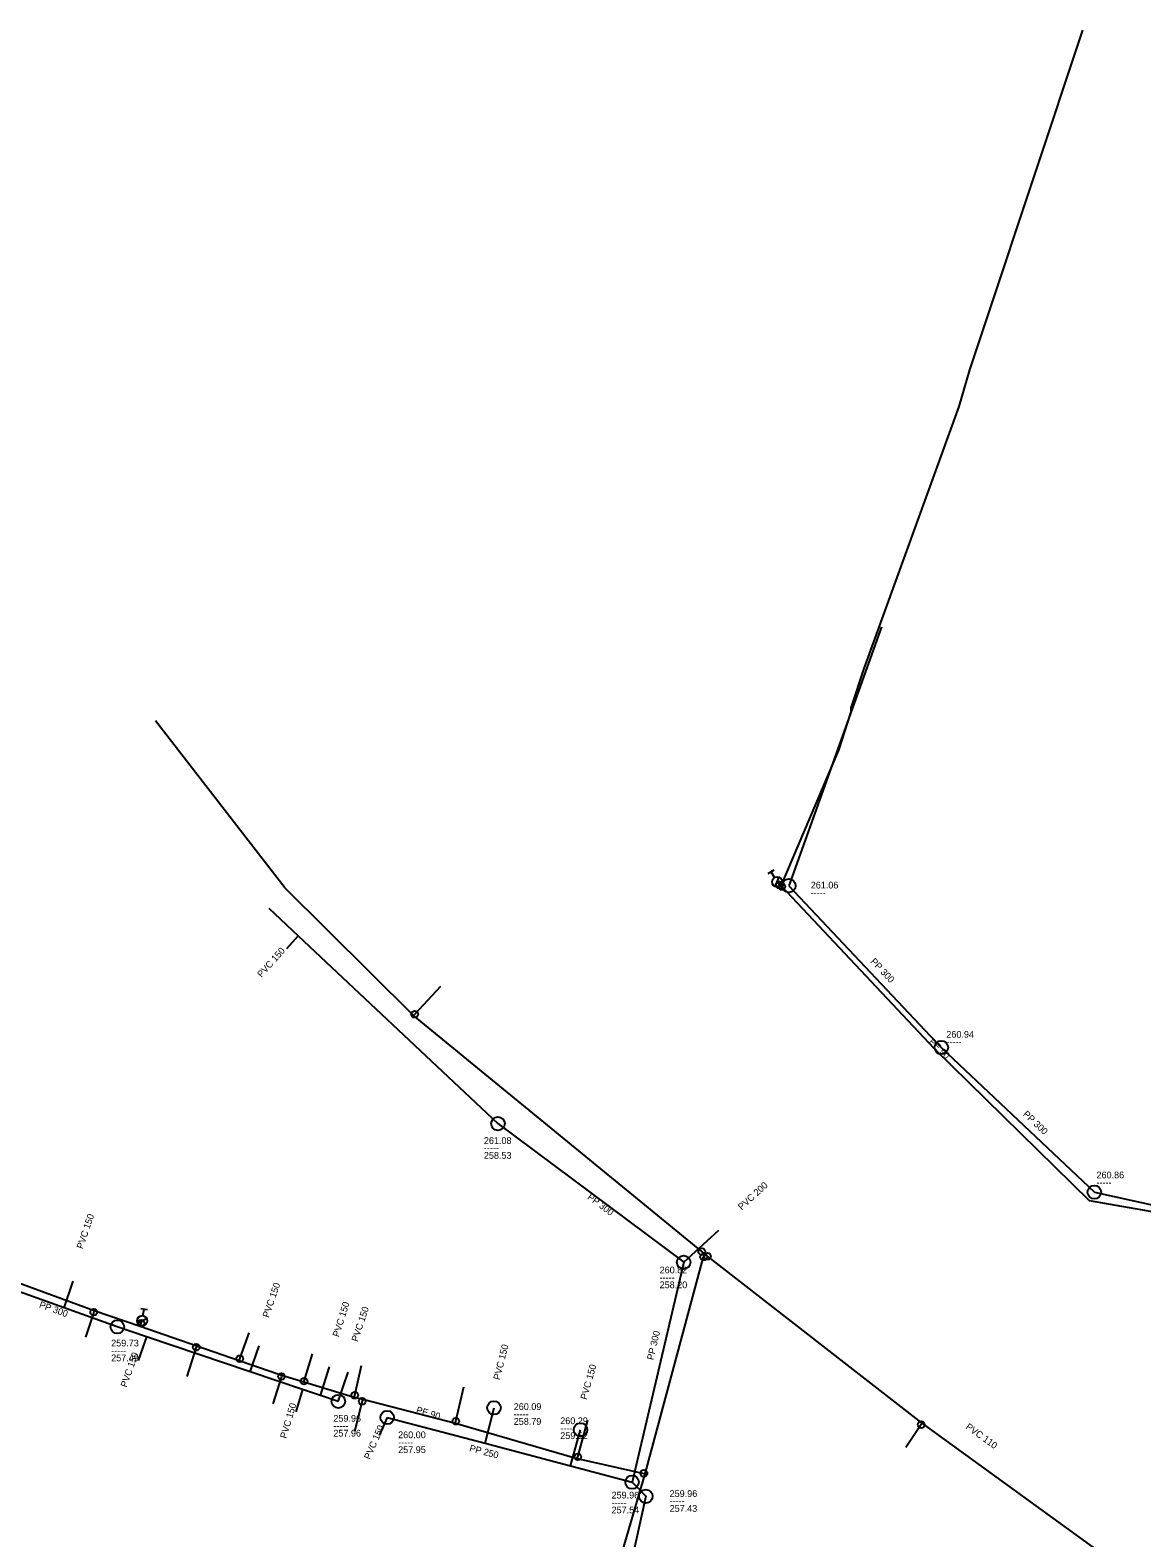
# Model space of a CAD drawing. Extents: x -771681 to -770485, y -1050143 to -1049574.
# Drawn here: x -771090.5 to -770925.9, y -1049898.6 to -1049675.1 of the extents above; entities that cross this region are included whole.
import ezdxf

# ---------------------------------------------------------------- set-up
doc = ezdxf.new("R2010")
doc.units = 0
doc.layers.add('Level 0', color=7, linetype='Continuous')

msp = doc.modelspace()

# ---------------------------------------------------------------- linework, layer by layer
at = {"layer": 'Level 0'}
for p, q in [((-770934.63, -1049675.12), (-770948.99, -1049718.19)), ((-770948.99, -1049718.19), (-770951.4, -1049725.46)), ((-770951.4, -1049725.46), (-770952.95, -1049730.91)), ((-770952.95, -1049730.91), (-770967.04, -1049769.75)), ((-770964.4, -1049763.54), (-770978.14, -1049801.92)), ((-770967.04, -1049769.75), (-770968.94, -1049775.57)), ((-770968.96, -1049776.14), (-770970.78, -1049781.83)), ((-770968.94, -1049775.57), (-770968.96, -1049776.14)), ((-771052.81, -1049802.25), (-771071.95, -1049777.49)), ((-770970.78, -1049781.83), (-770979.33, -1049801.95)), ((-770981.19, -1049800.09), (-770980.32, -1049799.59)), ((-770980.26, -1049800.71), (-770980.76, -1049799.84)), ((-770980.16, -1049802.05), (-770979.6, -1049800.66)), ((-770979.52, -1049801.81), (-770979.88, -1049801.36)), ((-771033.72, -1049821.15), (-771052.81, -1049802.25)), ((-770979.33, -1049801.95), (-770979.52, -1049801.81)), ((-770979.19, -1049802.05), (-770979.33, -1049801.95)), ((-770956.57, -1049826.09), (-770979.19, -1049802.05)), ((-770978.14, -1049801.92), (-770955.57, -1049825.89)), ((-771055.15, -1049805.27), (-771050.81, -1049809.36)), ((-771050.81, -1049809.36), (-771052.52, -1049811.28)), ((-771050.81, -1049809.36), (-771021.23, -1049837.18)), ((-771033.56, -1049820.97), (-771029.71, -1049816.81)), ((-771033.72, -1049821.15), (-771033.56, -1049820.97)), ((-770991.04, -1049856.14), (-771033.72, -1049821.15)), ((-770955.57, -1049825.89), (-770932.9, -1049847.34)), ((-770933.62, -1049848.6), (-770956.57, -1049826.09)), ((-771021.23, -1049837.18), (-770993.72, -1049857.73)), ((-770932.9, -1049847.34), (-770918.82, -1049850.46)), ((-770921.78, -1049850.71), (-770933.62, -1049848.6)), ((-770993.72, -1049857.73), (-770988.5, -1049852.98)), ((-771101.81, -1049857.24), (-771081.01, -1049864.88)), ((-770999.4, -1049889.07), (-770990.76, -1049856.93)), ((-770990.49, -1049856.6), (-770991.04, -1049856.14)), ((-770990.76, -1049856.93), (-770990.49, -1049856.6)), ((-770990.2, -1049856.84), (-770990.49, -1049856.6)), ((-770958.39, -1049881.57), (-770990.2, -1049856.84)), ((-770993.72, -1049857.73), (-771001.36, -1049890.32)), ((-771085.49, -1049864.48), (-771094.02, -1049861.43)), ((-771085.49, -1049864.48), (-771084.16, -1049860.54)), ((-771077.6, -1049867.3), (-771085.49, -1049864.48)), ((-771081.09, -1049865.13), (-771082.31, -1049868.84)), ((-771081.01, -1049864.88), (-771081.09, -1049865.13)), ((-771081.01, -1049864.88), (-771074.23, -1049867.21)), ((-771074.59, -1049866.74), (-771073.27, -1049866.04)), ((-771074.12, -1049864.58), (-771073.13, -1049864.75)), ((-771073.8, -1049865.65), (-771073.63, -1049864.67)), ((-771073.28, -1049868.76), (-771077.6, -1049867.3)), ((-771074.23, -1049867.21), (-771074.08, -1049866.75)), ((-771074.23, -1049867.21), (-771065.84, -1049870.09)), ((-771074.08, -1049866.75), (-771073.93, -1049866.39)), ((-771059.47, -1049872.02), (-771058.08, -1049868.19)), ((-771073.28, -1049868.76), (-771074.52, -1049872.29)), ((-771057.9, -1049873.95), (-771073.28, -1049868.76)), ((-771065.91, -1049870.32), (-771067.31, -1049874.68)), ((-771065.84, -1049870.09), (-771065.91, -1049870.32)), ((-771065.84, -1049870.09), (-771059.56, -1049872.27)), ((-771057.9, -1049873.95), (-771056.58, -1049870.1)), ((-771059.56, -1049872.27), (-771059.47, -1049872.02)), ((-771059.56, -1049872.27), (-771053.69, -1049874.32)), ((-771049.95, -1049875.35), (-771048.71, -1049871.3)), ((-771050.17, -1049876.56), (-771057.9, -1049873.95)), ((-771053.28, -1049874.66), (-771054.58, -1049878.73)), ((-771053.69, -1049874.32), (-771053.22, -1049874.46)), ((-771053.22, -1049874.46), (-771053.28, -1049874.66)), ((-771053.22, -1049874.46), (-771049.98, -1049875.45)), ((-771047.51, -1049877.46), (-771046.19, -1049873.23)), ((-771044.87, -1049878.35), (-771043.42, -1049874.02)), ((-771042.44, -1049877.44), (-771041.43, -1049873.01)), ((-771050.17, -1049876.56), (-771051.15, -1049879.91)), ((-771047.51, -1049877.46), (-771050.17, -1049876.56)), ((-771049.98, -1049875.45), (-771049.95, -1049875.35)), ((-771049.98, -1049875.45), (-771042.5, -1049877.7)), ((-771044.87, -1049878.35), (-771047.51, -1049877.46)), ((-771042.5, -1049877.7), (-771042.44, -1049877.44)), ((-771027.47, -1049881.29), (-771026.27, -1049876.2)), ((-771042.5, -1049877.7), (-771041.25, -1049878.02)), ((-771041.33, -1049878.33), (-771042.47, -1049882.81)), ((-771041.25, -1049878.02), (-771041.33, -1049878.33)), ((-771041.25, -1049878.02), (-771027.53, -1049881.55)), ((-771023.14, -1049884.56), (-771021.81, -1049879.32)), ((-771037.64, -1049880.73), (-771038.8, -1049883.39)), ((-771037.64, -1049880.73), (-771023.14, -1049884.56)), ((-771027.53, -1049881.55), (-771027.47, -1049881.29)), ((-771027.53, -1049881.55), (-771009.47, -1049886.82)), ((-771009.4, -1049886.56), (-771007.92, -1049881.13)), ((-770958.54, -1049881.79), (-770960.82, -1049885.2)), ((-770958.39, -1049881.57), (-770958.54, -1049881.79)), ((-770928.56, -1049903.22), (-770958.39, -1049881.57)), ((-771010.5, -1049887.9), (-771009, -1049882.55)), ((-771023.14, -1049884.56), (-771010.5, -1049887.9)), ((-771010.5, -1049887.9), (-771001.36, -1049890.32)), ((-771009.47, -1049886.82), (-771009.4, -1049886.56)), ((-771009.47, -1049886.82), (-770999.61, -1049889.01)), ((-771002.75, -1049900.38), (-770999.4, -1049889.07)), ((-771001.36, -1049890.32), (-770999.32, -1049892.41)), ((-770999.61, -1049889.01), (-770999.4, -1049889.07)), ((-770999.32, -1049892.41), (-771001.56, -1049902.49))]:
    msp.add_line(p, q, dxfattribs=at)
for centre, radius in [((-770979.88, -1049801.36), 0.75), ((-770979.52, -1049801.81), 0.5), ((-770978.14, -1049801.92), 1), ((-770979.19, -1049802.05), 0.5), ((-771033.56, -1049820.97), 0.5), ((-770955.57, -1049825.89), 1), ((-771021.23, -1049837.18), 1), ((-770932.9, -1049847.34), 1), ((-770993.72, -1049857.73), 1), ((-770991.04, -1049856.14), 0.5), ((-770990.76, -1049856.93), 0.5), ((-770990.2, -1049856.84), 0.5), ((-771081.09, -1049865.13), 0.5), ((-771073.93, -1049866.39), 0.75), ((-771074.08, -1049866.75), 0.5), ((-771077.6, -1049867.3), 1), ((-771065.91, -1049870.32), 0.5), ((-771059.47, -1049872.02), 0.5), ((-771053.28, -1049874.66), 0.5), ((-771049.95, -1049875.35), 0.5), ((-771044.87, -1049878.35), 1), ((-771042.44, -1049877.44), 0.5), ((-771041.33, -1049878.33), 0.5), ((-771021.82, -1049879.3), 1), ((-771037.64, -1049880.73), 1), ((-771027.47, -1049881.29), 0.5), ((-771009, -1049882.55), 1), ((-770958.54, -1049881.79), 0.5), ((-771009.4, -1049886.56), 0.5), ((-770999.61, -1049889.01), 0.5), ((-771001.36, -1049890.32), 1), ((-770999.32, -1049892.41), 1)]:
    msp.add_circle(centre, radius, dxfattribs=at)

# ---------------------------------------------------------------- texts
for s, p in [('261.06', (-770974.9, -1049802.33)), ('-----', (-770974.9, -1049803.43)), ('260.94', (-770954.82, -1049824.45)), ('-----', (-770954.82, -1049825.55)), ('261.08', (-771023.31, -1049840.19)), ('-----', (-771023.31, -1049841.29)), ('258.53', (-771023.31, -1049842.39)), ('-----', (-770932.58, -1049846.39)), ('260.86', (-770932.58, -1049845.29)), ('260.82', (-770997.28, -1049859.37)), ('-----', (-770997.28, -1049860.47)), ('258.20', (-770997.28, -1049861.57)), ('259.73', (-771078.51, -1049870.2)), ('-----', (-771078.51, -1049871.3)), ('257.49', (-771078.51, -1049872.4)), ('260.09', (-771018.89, -1049879.62)), ('259.96', (-771045.6, -1049881.36)), ('-----', (-771018.89, -1049880.72)), ('258.79', (-771018.89, -1049881.82)), ('260.29', (-771012, -1049881.72)), ('-----', (-771045.6, -1049882.46)), ('257.96', (-771045.6, -1049883.56)), ('260.00', (-771036.01, -1049883.8)), ('-----', (-771012, -1049882.82)), ('259.52', (-771012, -1049883.92)), ('-----', (-771036.01, -1049884.9)), ('257.95', (-771036.01, -1049886)), ('259.96', (-771004.4, -1049892.74)), ('259.96', (-770995.8, -1049892.51)), ('-----', (-771004.4, -1049893.84)), ('257.54', (-771004.4, -1049894.94)), ('-----', (-770995.8, -1049893.61)), ('257.43', (-770995.8, -1049894.71))]:
    msp.add_text(s, height=1, dxfattribs=at).set_placement(p)
for s, rotation, p in [('PVC 150', 48.311, (-771056.23, -1049815.61)), ('PP 300', 313.277, (-770966.13, -1049813.22)), ('PE 90', 315.555, (-770957.48, -1049825.13)), ('PP 300', 316.584, (-770943.55, -1049835.89)), ('PVC 200', 42.301, (-770985.13, -1049850.06)), ('PP 300', 323.24, (-771008.07, -1049848.26)), ('PVC 150', 71.347, (-771082.72, -1049855.83)), ('PVC 150', 71.075, (-771055.18, -1049866.02)), ('PP 300', 340.325, (-771089.26, -1049864.41)), ('PVC 150', 72.669, (-771044.79, -1049868.88)), ('PVC 150', 71.486, (-771042.01, -1049869.58)), ('PP 300', 76.807, (-770998.21, -1049872.28)), ('PVC 150', 75.758, (-771020.97, -1049875.23)), ('PVC 150', 70.645, (-771076.22, -1049876.34)), ('PVC 150', 74.338, (-771008.08, -1049878.17)), ('PVC 150', 73.694, (-771052.57, -1049883.91)), ('PE 90', 343.259, (-771033.42, -1049880.03)), ('PVC 150', 66.438, (-771040.19, -1049887.04)), ('PVC 110', 324.029, (-770952.05, -1049882.31)), ('PP 250', 345.198, (-771025.53, -1049885.71))]:
    msp.add_text(s, height=1, rotation=rotation, dxfattribs=at).set_placement(p)

doc.saveas('drawing.dxf')
